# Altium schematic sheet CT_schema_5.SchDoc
size 258 x 163 mm
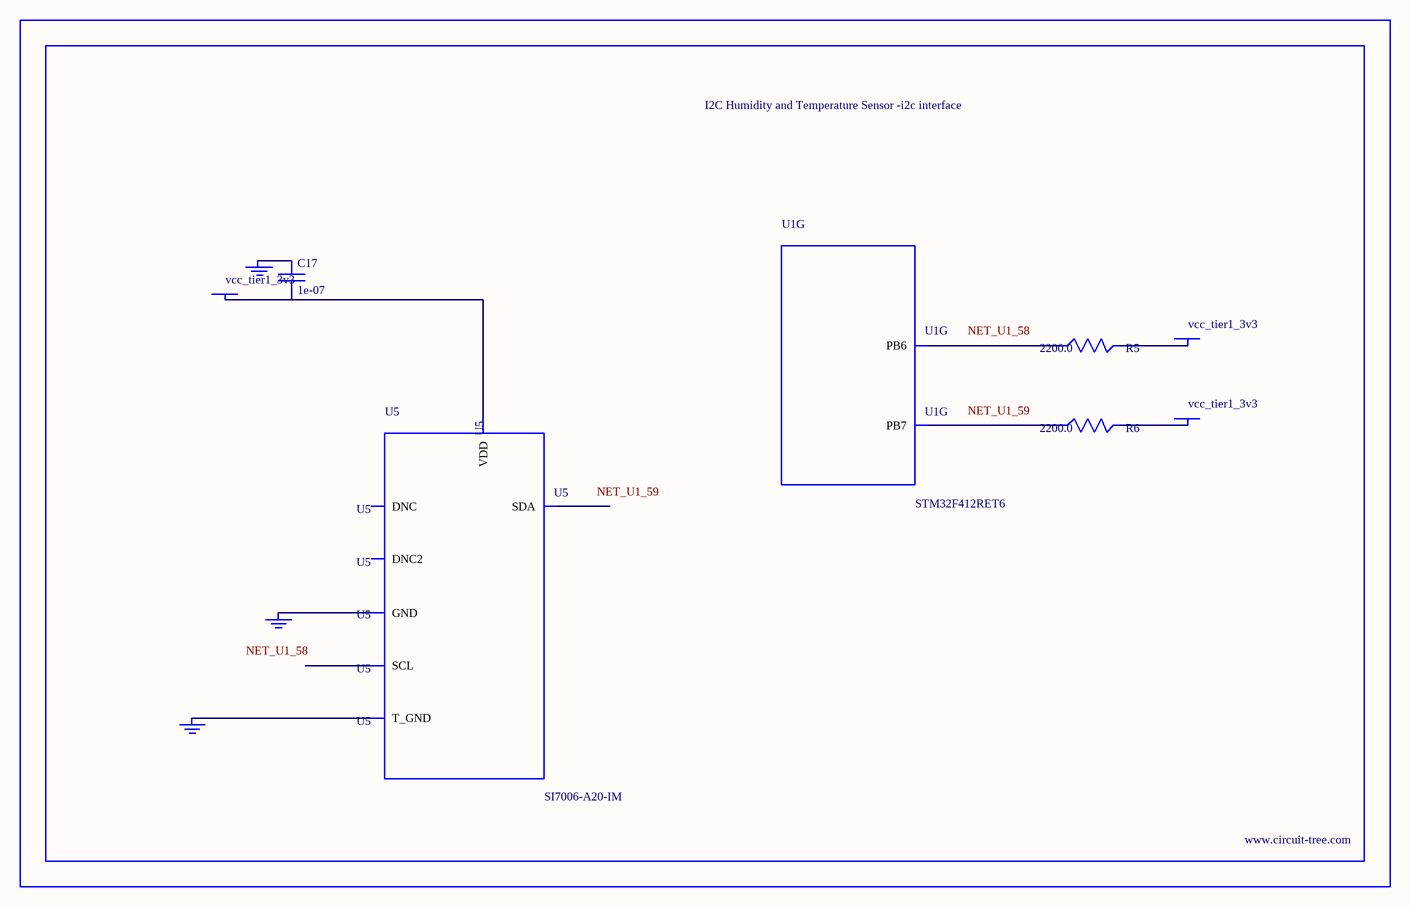
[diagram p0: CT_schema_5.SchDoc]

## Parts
BORDER4  (no value)
C17  1e-07  [C0402]
GND_INSTANCE_4_0  (no value)
GND_INSTANCE_4_1  (no value)
GND_INSTANCE_4_2  (no value)
POWER_INSTANCE_4_0  vcc_tier1_3v3
POWER_INSTANCE_4_1  vcc_tier1_3v3
POWER_INSTANCE_4_2  vcc_tier1_3v3
R5  2200.0  [R0603]
R6  2200.0  [R0603]
U1  STM32F412RET6  [LQFP64]  (part G of 9)
U5  SI7006-A20-IM  [DFN-6]

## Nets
NetC17_1: C17.1 GND_INSTANCE_4_0.0(GND)
NetC17_2: C17.2 POWER_INSTANCE_4_0.0(PWR) U5.5(VDD)
NetGND_INSTANCE_4_1_0: GND_INSTANCE_4_1.0(GND) U5.7(T_GND)
NetGND_INSTANCE_4_2_0: GND_INSTANCE_4_2.0(GND) U5.2(GND)
NetPOWER_INSTANCE_4_1_0: POWER_INSTANCE_4_1.0(PWR) R5.2
NetPOWER_INSTANCE_4_2_0: POWER_INSTANCE_4_2.0(PWR) R6.2
NetR5_1: R5.1 U1.58(PB6)
NetR6_1: R6.1 U1.59(PB7)

Not connected (* = marked no-connect by the designer): U5 1(SDA) 3(DNC) 4(DNC2) 6(SCL)

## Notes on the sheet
- Labels drawn without touching a wire or pin: NET_U1_58, NET_U1_59

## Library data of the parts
BORDER4 = BORDER_PAGE4
C17 = C0402C104K3RACTU
GND_INSTANCE_4_0-GND_INSTANCE_4_2 = GND
POWER_INSTANCE_4_0-POWER_INSTANCE_4_2 = PWR
R5 R6 = RC0603JR-072K2L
